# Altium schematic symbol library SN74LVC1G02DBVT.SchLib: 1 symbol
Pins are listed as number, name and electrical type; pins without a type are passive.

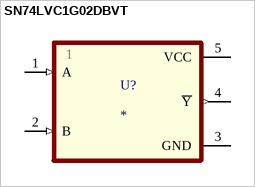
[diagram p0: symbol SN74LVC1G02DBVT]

## SN74LVC1G02DBVT
designator U?
NOR IC 1 canal SOT-23-5; MF: Texas Instruments; MP: SN74LVC1G02DBV
footprint SOT23-5
pins: 1 A (in), 2 B (in), 3 GND, 4 ~{Y} (out), 5 VCC (power)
